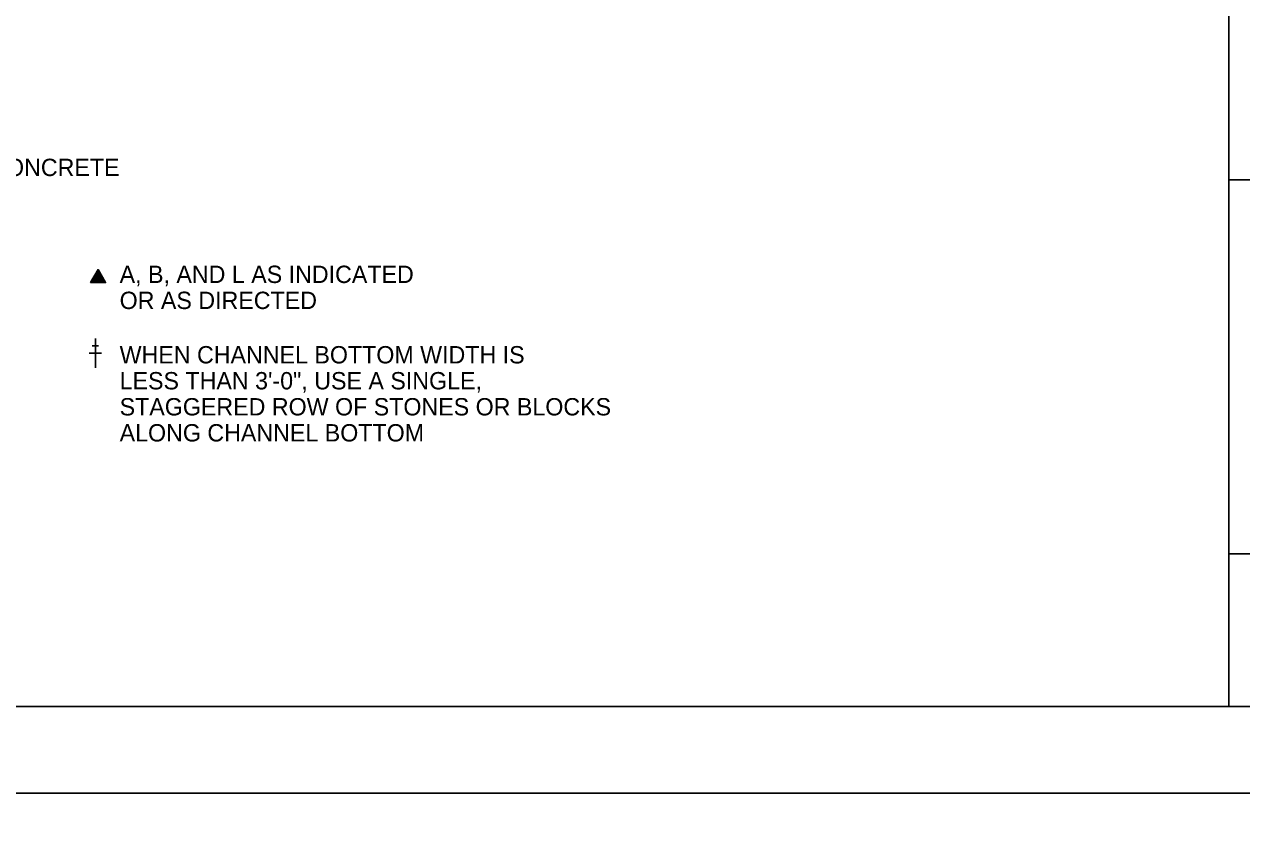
# Model space of a CAD drawing. Extents: x 636183 to 639890, y 299162 to 300538.
# Drawn here: x 638561.9 to 638772.1, y 299936.9 to 300077.3 of the extents above; entities that cross this region are included whole.
import ezdxf

# ---------------------------------------------------------------- set-up
doc = ezdxf.new("R2010")
doc.units = 0
for name, color, linetype in [('1', 7, 'Continuous'), ('Default', 7, 'Continuous'), ('PLT-BNDY', 7, 'Continuous')]:
    doc.layers.add(name, color=color, linetype=linetype)

# ---------------------------------------------------------------- blocks, each defined once
blk = doc.blocks.new('CT')
at = {"layer": 'Default'}
for p, q in [((-0.094, -0.277), (-0.271, 0.031)), ((-0.053, -0.277), (-0.251, 0.066)), ((-0.012, -0.277), (-0.23, 0.102)), ((0.03, -0.277), (-0.21, 0.138)), ((0.071, -0.277), (-0.189, 0.173)), ((0.112, -0.277), (-0.168, 0.209)), ((0.153, -0.277), (-0.148, 0.245)), ((0.195, -0.277), (-0.127, 0.281)), ((0.236, -0.277), (-0.106, 0.316)), ((0.277, -0.277), (-0.086, 0.352)), ((0.318, -0.277), (-0.065, 0.388)), ((0.36, -0.277), (-0.044, 0.423)), ((0.401, -0.277), (-0.024, 0.459)), ((0.442, -0.277), (-0.003, 0.495)), ((-0.424, -0.277), (-0.436, -0.255)), ((-0.383, -0.277), (-0.416, -0.219)), ((-0.342, -0.277), (-0.395, -0.184)), ((-0.3, -0.277), (-0.374, -0.148)), ((-0.259, -0.277), (-0.354, -0.112)), ((-0.218, -0.277), (-0.333, -0.077)), ((-0.177, -0.277), (-0.313, -0.041)), ((-0.135, -0.277), (-0.292, -0.005))]:
    blk.add_line(p, q, dxfattribs=at)
blk.add_lwpolyline([(-0.448, -0.277), (0.444, -0.277), (-0.002, 0.497)], close=True, dxfattribs=at)
blk = doc.blocks.new('CROSS')
at = {"layer": 'Default'}
for p, q in [((0, 0.436), (0, -0.435)), ((0, 0.436), (0, 0)), ((-0.182, 0), (0, 0)), ((-0.096, 0.218), (0, 0.218)), ((0, 0.218), (0.096, 0.218)), ((0, 0), (0.182, 0))]:
    blk.add_line(p, q, dxfattribs=at)

msp = doc.modelspace()

# ---------------------------------------------------------------- linework, layer by layer
at = {"layer": '1'}
msp.add_lwpolyline([(638969.91, 299959.45), (638969.91, 300523.45), (638183.91, 300523.45), (638183.91, 299959.45), (638969.91, 299959.45), (638969.91, 299985.81), (638769.91, 299985.81), (638769.91, 300050.49), (638969.91, 300050.49), (638969.91, 300079.45), (638769.91, 300079.45), (638769.91, 299959.45), (638848.72, 299959.45), (638848.72, 299985.81), (638848.72, 299959.45), (638925.72, 299959.45), (638925.72, 299985.81), (638925.72, 299973.49), (638969.91, 299973.49)], dxfattribs=at)
at = {"layer": 'PLT-BNDY'}
for points in [[(638143.91, 300538.45), (638984.91, 300538.45), (638984.91, 299944.45), (638143.91, 299944.45)], [(638143.91, 299944.45), (638984.91, 299944.45), (638984.91, 299350.45), (638143.91, 299350.45)]]:
    msp.add_lwpolyline(points, close=True, dxfattribs=at)

# ---------------------------------------------------------------- block references
at = {"layer": 'Default'}
for name, p, xscale, yscale in [('CT', (638574.67, 300033.51), 2.901199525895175, 2.901199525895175), ('CROSS', (638574.21, 300020.53), 5.80239905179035, 5.80239905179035)]:
    msp.add_blockref(name, p, dxfattribs=dict(at, xscale=xscale, yscale=yscale))

# ---------------------------------------------------------------- texts
for s, p in [('CLASS A CEMENT CONCRETE', (638519.79, 300051.12)), ('A, B, AND L AS INDICATED', (638578.39, 300032.64)), ('OR AS DIRECTED', (638578.39, 300028.14)), ('WHEN CHANNEL BOTTOM WIDTH IS', (638578.39, 300018.74)), ('LESS THAN 3\'-0", USE A SINGLE,', (638578.39, 300014.25)), ('STAGGERED ROW OF STONES OR BLOCKS', (638578.39, 300009.75)), ('ALONG CHANNEL BOTTOM', (638578.39, 300005.25))]:
    msp.add_text(s, height=2.998, dxfattribs=at).set_placement(p)

doc.saveas('drawing.dxf')
